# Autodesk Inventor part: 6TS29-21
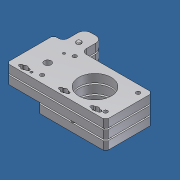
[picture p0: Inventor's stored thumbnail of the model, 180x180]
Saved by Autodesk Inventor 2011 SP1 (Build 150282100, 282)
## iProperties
Created: 2011-05
Part Number: 6TS29-21
Document SubType Name: Modeling
Designer: Darius
Density: 1 g/cm^3
Author: Darius
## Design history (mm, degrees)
feature "Base1"
body "Solid1"
